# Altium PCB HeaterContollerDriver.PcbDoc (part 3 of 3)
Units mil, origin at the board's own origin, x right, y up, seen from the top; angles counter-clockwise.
Board outline 11550 x 4775 mil, 6 copper layers (Top Layer, GND1, P, N, GND2, Bottom Layer), stack 62.668 mil thick; 274 components, 133 nets, 711 pads, 145 vias.
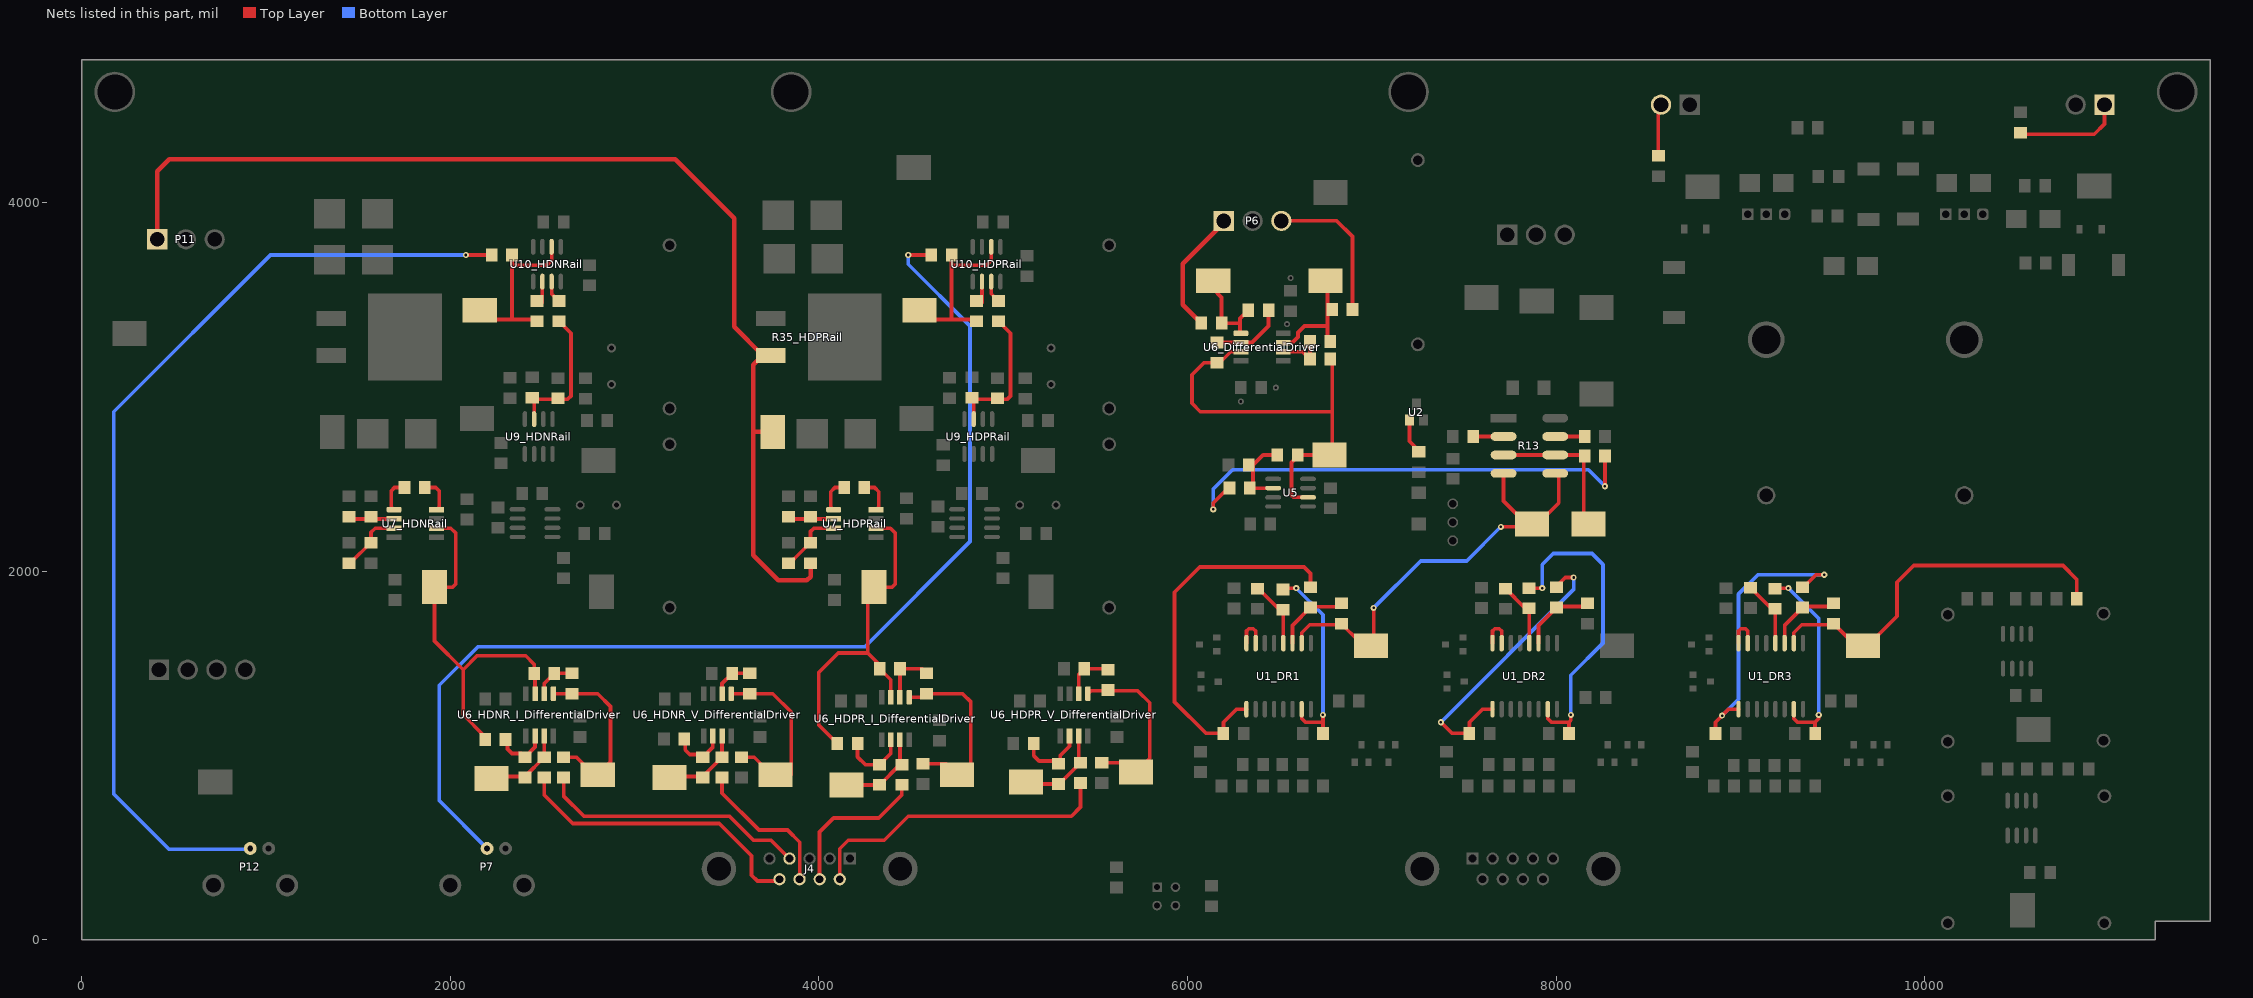
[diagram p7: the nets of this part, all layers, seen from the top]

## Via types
v1: diameter 33, hole 14, Top Layer to Bottom Layer, 145 vias

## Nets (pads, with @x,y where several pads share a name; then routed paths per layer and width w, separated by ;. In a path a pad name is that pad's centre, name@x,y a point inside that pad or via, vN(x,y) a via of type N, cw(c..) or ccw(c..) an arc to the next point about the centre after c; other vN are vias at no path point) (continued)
NetJ4_4: J4.4 R28_HDNR_I_DifferentialDriver.2 | length 1476.4
  Top Layer w20: R28_HDNR_I_DifferentialDriver.2@2615.12,879.88 2615.12,780.12 2725.24,670 3515,670 3645,540 3740,540 3842,438 J4.4@3842,430
NetJ4_6: J4.6 R31_HDPR_V_DifferentialDriver.2 | length 1695.6
  Top Layer w20: J4.6@4113.58,328.09 4113.58,493.58 4160,540 4355,540 4485,670 5370.12,670 5420,719.88 R31_HDPR_V_DifferentialDriver.2@5420,849.88
NetJ4_7: J4.7 R31_HDPR_I_DifferentialDriver.2 | length 850.1
  Top Layer w20: J4.7@4004,318 4004,584 4080,660 4325,660 4450,785 R31_HDPR_I_DifferentialDriver.2@4450,839.88
NetJ4_8: J4.8 R31_HDNR_V_DifferentialDriver.2 | length 826.9
  Top Layer w20: R31_HDNR_V_DifferentialDriver.2@3475,879.76 3475,795 3675,595 3830,595 3896,529 J4.8@3896,318
NetJ4_9: J4.9 R31_HDNR_I_DifferentialDriver.2 | length 1627.8
  Top Layer w20: R31_HDNR_I_DifferentialDriver.2@2510.12,879.88 2510.12,784.88 2665,630 3460,630 3635,455 3635,350 3667,318 J4.9@3788,318
NetP7_1: P7.1 R46_HDPRail.2 | length 6014.4
  Top Layer w20: v1(4485,3715) R46_HDPRail.2@4609.88,3715
  Bottom Layer w20: P7.1@2200,495 1940,755 1940,1380 2150,1590 4250,1590 4820,2160 4820,3330 4485,3665 v1(4485,3715)
NetP12_1: P12.1 R46_HDNRail.2 | length 5350.4
  Top Layer w20: v1(2085,3715) R46_HDNRail.2@2224.88,3715
  Bottom Layer w20: P12.1@920,500 910,490 475,490 175,790 175,2865 1025,3715 v1(2085,3715)
NetP13_1: P13.1 R53.1 | length 572.8
  Top Layer w20: R53.1@10520.12,4370.5 10920.12,4370.5 10975.12,4425.5 P13.1@10975.12,4520.5
NetP14_2: P14.2 R54.1 | length 275.8
  Top Layer w20: R54.1@8555,4260.5 8555,4516.5 P14.2@8569,4530.5
NetR1_DR1_1: R1_DR1.1 R3_DR1.1 U1_DR1.12 | length 324
  Top Layer w20: R3_DR1.1@6380,1910.12 R1_DR1.1@6492.95,1797.17 ; R1_DR1.1@6517.24,1772.17 6519.88,1769.53 U1_DR1.12@6519.88,1609.02
NetR1_DR1_2: R1_DR1.2 R5_DR1.1 U1_DR1.7 | length 1108.8
  Top Layer w20: R1_DR1.2@6517.24,1907.4 v1(6590,1907.4) ; U1_DR1.7@6619.88,1264.76 6619.88,1199.88 6640,1179.76 6735,1179.76 ; v1(6735,1219.76) 6735,1179.76 ; R5_DR1.1@6735.12,1119.76 6735,1119.88 6735,1179.76
  Bottom Layer w20: v1(6590,1907.4) 6735,1762.4 v1(6735,1219.76)
NetR1_DR2_1: R1_DR2.1 R3_DR2.1 U1_DR2.12 | length 336.2
  Top Layer w20: R3_DR2.1@7725,1905.12 7832.83,1797.28 R1_DR2.1@7852.24,1797.28 ; R1_DR2.1@7852.24,1772.28 7854.88,1769.65 U1_DR2.12@7854.88,1609.13
NetR1_DR2_2: R1_DR2.2 R5_DR2.1 U1_DR2.7 | length 1760.1
  Top Layer w20: R1_DR2.2@7852.24,1907.52 v1(7925,1907.52) ; U1_DR2.7@7954.88,1264.88 U1_DR2.7@7954.88,1250.87 7954.88,1200 7975,1179.88 8070,1179.88 ; R5_DR2.1@8070.12,1119.88 8070,1120 8070,1179.88 ; v1(8080,1219.76) 8080,1189.88 8070,1179.88
  Bottom Layer w20: v1(7925,1907.52) 7925,2035 7985,2095 8195,2095 8255,2035 8255,1610 8080,1435 v1(8080,1219.76)
NetR1_DR3_1: R1_DR3.1 R3_DR3.1 U1_DR3.12 | length 323.8
  Top Layer w20: R3_DR3.1@9055,1910.12 R1_DR3.1@9167.83,1797.28 ; R1_DR3.1@9187.24,1772.28 9189.88,1769.65 U1_DR3.12@9189.88,1609.13
NetR1_DR3_2: R1_DR3.2 R5_DR3.1 U1_DR3.7 | length 1125.4
  Top Layer w20: R1_DR3.2@9187.24,1907.52 v1(9260,1907.52) ; U1_DR3.7@9289.88,1264.88 U1_DR3.7@9289.88,1250.87 9289.88,1200 9310,1179.88 9405,1179.88 ; R5_DR3.1@9405.12,1119.88 9405,1120 9405,1179.88 ; v1(9425,1220) 9425,1199.88 9405,1179.88
  Bottom Layer w20: v1(9260,1907.52) 9425,1742.52 v1(9425,1220)
NetR8_DR1_1: R8_DR1.1 R11_DR1.2 U1_DR1.1 | length 2173.5
  Top Layer w20: U1_DR1.1@6319.88,1250.75 6265.87,1250.75 6195,1179.88 6195,1119.76 6100,1119.76 5930,1289.76 5930,1885 6067.28,2022.28 6632.24,2022.28 ; 6487.28,2022.28 6632.24,2022.28 ; R11_DR1.2@6667.24,1912.4 6667.24,1987.28 6632.24,2022.28
NetR8_DR2_1: R8_DR2.1 R11_DR2.2 U1_DR2.1 | length 1594.8
  Top Layer w20: v1(7375,1179.88) 7435,1119.88 7530,1119.88 7530,1180 7600.87,1250.87 U1_DR2.1@7654.88,1250.87 ; R11_DR2.2@8002.24,1912.52 8002.24,1917.24 8050,1965 v1(8095,1965)
  Bottom Layer w20: v1(7375,1179.88) 8095,1899.88 v1(8095,1965)
NetR8_DR3_1: R8_DR3.1 R11_DR3.2 U1_DR3.1 | length 1572.7
  Top Layer w20: R8_DR3.1@8865,1119.88 8865,1180 v1(8900.43,1215.43) 8935.87,1250.87 U1_DR3.1@8989.88,1250.87 ; R11_DR3.2@9337.24,1912.52 9337.24,1907.24 9410,1980 v1(9455,1980)
  Bottom Layer w20: v1(8900.43,1215.43) 8990,1305 8990,1875 9095,1980 v1(9455,1980)
NetR9_DR1_1: R9_DR1.1 R13.4 R13.5 TP1_DR1.1 TP2.1 U1_DR1.10 | length 2493.4
  Top Layer w20: U1_DR1.10@6619.88,1609.02 6619.88,1664.92 6663.23,1708.27 6828.5,1708.27 R9_DR1.1@6835,1714.76 6932.24,1617.52 6932.24,1622.52 TP1_DR1.1@6990,1564.76 ; TP1_DR1.1@6995,1594.76 7010,1609.76 v1(7010,1799.88) ; v1(7700,2239.88) 7854.88,2239.88 TP2.1@7870,2255 ; R13.4@7715,2530 7715,2380 7840,2255 TP2.1@7870,2255 ; R13.5@7995,2530 8015,2510 8015,2370 7915,2270 7885,2270 TP2.1@7870,2255
  Bottom Layer w20: v1(7010,1799.88) 7265.12,2055 7515.12,2055 v1(7700,2239.88)
NetR9_DR1_2: R9_DR1.2 R11_DR1.1 U1_DR1.11 | length 410.8
  Top Layer w20: U1_DR1.11@6569.88,1609.02 6569.88,1704.92 6672.24,1807.28 6817.28,1807.28 R9_DR1.2@6835,1825
NetR9_DR2_2: R9_DR2.2 R11_DR2.1 U1_DR2.11 | length 410.8
  Top Layer w20: U1_DR2.11@7904.88,1609.13 7904.88,1705.04 8007.24,1807.4 8152.28,1807.4 R9_DR2.2@8170,1825.12
NetR9_DR3_1: R9_DR3.1 R19.2 TP1_DR3.1 U1_DR3.10 | length 2100.6
  Top Layer w20: U1_DR3.10@9289.88,1609.13 9289.88,1665.04 9333.23,1708.39 9498.5,1708.39 R9_DR3.1@9505,1714.88 9602.24,1617.64 9602.24,1622.64 TP1_DR3.1@9660,1564.88 ; TP1_DR3.1@9665,1594.88 9689.88,1594.88 9850,1755 9850,1940 9940,2030 10750,2030 10825.12,1954.88 R19.2@10825.12,1850
NetR9_DR3_2: R9_DR3.2 R11_DR3.1 U1_DR3.11 | length 410.8
  Top Layer w20: U1_DR3.11@9239.88,1609.13 9239.88,1705.04 9342.24,1807.4 9487.28,1807.4 R9_DR3.2@9505,1825.12
NetR13_2: R13.2 R15.1 | length 164.9
  Top Layer w20: R15.1@7550.12,2730 R13.2@7715,2730
NetR13_3: R13.3 R13.6 R16.2 TP3.1 | length 821.2
  Top Layer w20: R13.3@7715,2630 R13.6@7995,2630 8150,2630 8150,2265 TP3.1@8165,2250
NetR13_7: R13.7 R14.2 | length 160
  Top Layer w20: R13.7@7995,2730 R14.2@8155,2730
NetR16_1: R16.1 R24.1 | length 2643.5
  Top Layer w20: v1@6140,2330 v1(6140,2335) 6140,2370 6220,2450 R24.1@6229.49,2450 ; v1@8265,2460 v1(8265.12,2460.12) R16.1@8265.12,2625
  Bottom Layer w20: v1(6140,2335) 6140,2445 6245,2550 8175.24,2550 v1(8265.12,2460.12)
NetR17_2: R17.2 U2.1 | length 185.7
  Top Layer w20: U2.1@7205,2820 7205,2705 R17.2@7255,2655
NetR23_1: R23.1 R24.2 R25.2 U5.2 | length 381.3
  Top Layer w20: U5.2@6465,2450 6355.49,2450 6355.49,2575 6410.49,2630 R23.1@6479.49,2630
NetR23_2: R23.2 R27_DifferentialDriver.1 R30_DifferentialDriver.1 TP7.1 U5.6 U6_DifferentialDriver.3 | length 2297.8
  Top Layer w20: U6_DifferentialDriver.3@6290,3190 6234.88,3190 6174.76,3129.88 R27_DifferentialDriver.1@6159.88,3129.88 6089.88,3129.88 6025,3065 6025,2910 6070,2865 6785,2865 ; U5.6@6653.98,2400 6574.49,2400 6564.49,2410 6564.49,2589 6605.49,2630 6784.49,2630 6785,2630.51 6785,2865 ; R30_DifferentialDriver.1@6784.49,3140.51 R30_DifferentialDriver.1@6775,3150 6785,3140 6785,2865
NetR26_DifferentialDriver_1: R26_DifferentialDriver.1 R27_DifferentialDriver.2 U6_DifferentialDriver.2 | length 402.4
  Top Layer w20: R27_DifferentialDriver.2@6159.88,3240.12 6160,3240 U6_DifferentialDriver.2@6290,3240 6349.88,3240 6440,3330.12 R26_DifferentialDriver.1@6440,3415
NetR26_DifferentialDriver_2: R26_DifferentialDriver.2 R28_DifferentialDriver.1 TP8_DifferentialDriver.1 U6_DifferentialDriver.1 | length 508.4
  Top Layer w20: TP8_DifferentialDriver.1@6139.88,3585 6139.88,3530.12 6185,3485 R28_DifferentialDriver.1@6185,3345 6274.88,3345 6284.88,3335 ; U6_DifferentialDriver.1@6290,3290 6284.88,3295.12 6284.88,3335 ; R26_DifferentialDriver.2@6329.76,3415 6284.88,3370.12 6284.88,3335
NetR26_HDNR_I_DifferentialDriver_1: R26_HDNR_I_DifferentialDriver.1 R27_HDNR_I_DifferentialDriver.2 U6_HDNR_I_DifferentialDriver.2 | length 227.8
  Top Layer w20: U6_HDNR_I_DifferentialDriver.2@2510.12,1335 2510.12,1389.88 R27_HDNR_I_DifferentialDriver.2@2565.24,1445 2660,1445 R26_HDNR_I_DifferentialDriver.1@2660.12,1445.12
NetR26_HDNR_I_DifferentialDriver_2: R26_HDNR_I_DifferentialDriver.2 R28_HDNR_I_DifferentialDriver.1 TP8_HDNR_I_DifferentialDriver.1 U6_HDNR_I_DifferentialDriver.1 | length 962.1
  Top Layer w20: U6_HDNR_I_DifferentialDriver.1@2560.12,1335 R26_HDNR_I_DifferentialDriver.2@2660,1335 ; R28_HDNR_I_DifferentialDriver.1@2615.12,990.12 2684.88,990.12 2780,895 TP8_HDNR_I_DifferentialDriver.1@2800.12,895 2870,964.88 2870,1265 2800.12,1334.88 R26_HDNR_I_DifferentialDriver.2@2660.12,1334.88
NetR26_HDNR_V_DifferentialDriver_1: R26_HDNR_V_DifferentialDriver.1 R27_HDNR_V_DifferentialDriver.2 U6_HDNR_V_DifferentialDriver.2 | length 227.8
  Top Layer w20: U6_HDNR_V_DifferentialDriver.2@3475,1334.88 3475,1389.76 R27_HDNR_V_DifferentialDriver.2@3530.12,1444.88 3624.88,1444.88 R26_HDNR_V_DifferentialDriver.1@3625,1445
NetR26_HDNR_V_DifferentialDriver_2: R26_HDNR_V_DifferentialDriver.2 R28_HDNR_V_DifferentialDriver.1 TP8_HDNR_V_DifferentialDriver.1 U6_HDNR_V_DifferentialDriver.1 | length 1015.7
  Top Layer w20: U6_HDNR_V_DifferentialDriver.1@3525,1334.88 R26_HDNR_V_DifferentialDriver.2@3624.88,1334.88 ; R28_HDNR_V_DifferentialDriver.1@3580,990 3650,990 3745.12,894.88 TP8_HDNR_V_DifferentialDriver.1@3765,894.88 3850,894.88 3850,1235 3750.24,1334.76 R26_HDNR_V_DifferentialDriver.2@3625,1334.76
NetR26_HDPR_I_DifferentialDriver_1: R26_HDPR_I_DifferentialDriver.1 R27_HDPR_I_DifferentialDriver.2 U6_HDPR_I_DifferentialDriver.2 | length 275.3
  Top Layer w20: U6_HDPR_I_DifferentialDriver.2@4440,1315 4440,1469.88 R26_HDPR_I_DifferentialDriver.1@4560.24,1469.88 ; R26_HDPR_I_DifferentialDriver.1@4584.88,1445 R26_HDPR_I_DifferentialDriver.1@4585,1445.12
NetR26_HDPR_I_DifferentialDriver_2: R26_HDPR_I_DifferentialDriver.2 R28_HDPR_I_DifferentialDriver.1 TP8_HDPR_I_DifferentialDriver.1 U6_HDPR_I_DifferentialDriver.1 | length 1041.6
  Top Layer w20: U6_HDPR_I_DifferentialDriver.1@4490,1315 4565.12,1315 R26_HDPR_I_DifferentialDriver.2@4585,1334.88 4779.88,1334.88 4825,1289.76 4825,895 TP8_HDPR_I_DifferentialDriver.1@4750,895 4689.88,955.12 R28_HDPR_I_DifferentialDriver.1@4565,955.12
NetR26_HDPR_V_DifferentialDriver_1: R26_HDPR_V_DifferentialDriver.1 R27_HDPR_V_DifferentialDriver.2 U6_HDPR_V_DifferentialDriver.2 | length 272.8
  Top Layer w20: U6_HDPR_V_DifferentialDriver.2@5410,1334.88 5410,1439.88 R27_HDPR_V_DifferentialDriver.2@5440.12,1470 R26_HDPR_V_DifferentialDriver.1@5565.12,1470 ; R26_HDPR_V_DifferentialDriver.1@5559.88,1444.88 R26_HDPR_V_DifferentialDriver.1@5560,1445
NetR26_HDPR_V_DifferentialDriver_2: R26_HDPR_V_DifferentialDriver.2 R28_HDPR_V_DifferentialDriver.1 TP8_HDPR_V_DifferentialDriver.1 U6_HDPR_V_DifferentialDriver.1 | length 980.6
  Top Layer w20: U6_HDPR_V_DifferentialDriver.1@5460,1334.76 5475.24,1350 5730,1350 5795,1285 5795,984.65 TP8_HDPR_V_DifferentialDriver.1@5720,909.65 5669.53,960.12 R28_HDPR_V_DifferentialDriver.1@5535,960.12
NetR27_HDNR_I_DifferentialDriver_1: R27_HDNR_I_DifferentialDriver.1 R30_HDNR_I_DifferentialDriver.1 TP10_HDNRail.1 U6_HDNR_I_DifferentialDriver.3 U7_HDNRail.6 | length 2053.8
  Top Layer w20: U7_HDNRail.6@1925,2233 2003.12,2233 2030,2206.12 2030,1929.88 2013.12,1913 TP10_HDNRail.1@1915,1913 1915,1620 2070,1465 ; R30_HDNR_I_DifferentialDriver.1@2200,1105 2185,1105 2070,1220 2070,1465 ; R27_HDNR_I_DifferentialDriver.1@2455,1430 R27_HDNR_I_DifferentialDriver.1@2455,1445 2455,1495 2410,1540 2145,1540 2070,1465 ; U6_HDNR_I_DifferentialDriver.3@2460.12,1335 R27_HDNR_I_DifferentialDriver.1@2460.12,1439.88
NetR27_HDPR_I_DifferentialDriver_1: R27_HDPR_I_DifferentialDriver.1 R30_HDPR_I_DifferentialDriver.1 TP10_HDPRail.1 U6_HDPR_I_DifferentialDriver.3 U7_HDPRail.6 | length 1913.5
  Top Layer w20: R30_HDPR_I_DifferentialDriver.1@4099.88,1065 4000,1164.88 4000,1450 4105,1555 4265,1555 ; U7_HDPRail.6@4310,2233 4388.12,2233 4415,2206.12 4415,1929.88 4398.12,1913 TP10_HDPRail.1@4300,1913 4265,1878 4265,1555 ; U6_HDPR_I_DifferentialDriver.3@4390,1315 4390,1409.88 R27_HDPR_I_DifferentialDriver.1@4329.88,1470 4329.88,1490.12 4265,1555
NetR29_DifferentialDriver_1: R29_DifferentialDriver.1 R30_DifferentialDriver.2 U6_DifferentialDriver.6 | length 311.2
  Top Layer w20: U6_DifferentialDriver.6@6520,3190 6589.76,3190 ; U6_DifferentialDriver.6@6534.88,3190 6624.76,3190 R30_DifferentialDriver.2@6664.76,3150 R29_DifferentialDriver.1@6664.76,3245
NetR29_DifferentialDriver_2: R29_DifferentialDriver.2 R31_DifferentialDriver.1 TP9_DifferentialDriver.1 U6_DifferentialDriver.7 | length 647.3
  Top Layer w20: U6_DifferentialDriver.7@6520,3240 6569.88,3240 6599.88,3270 6599.88,3295 6634.88,3330 6749.88,3330 6760,3319.88 ; TP9_DifferentialDriver.1@6760,3590 6760,3319.88 ; R29_DifferentialDriver.2@6775,3245 6760,3260 6760,3319.88
NetR29_HDNR_I_DifferentialDriver_1: R29_HDNR_I_DifferentialDriver.1 R30_HDNR_I_DifferentialDriver.2 U6_HDNR_I_DifferentialDriver.6 | length 321.3
  Top Layer w20: R30_HDNR_I_DifferentialDriver.2@2310.24,1105 2310.24,1034.76 2335,1010 2385.24,1010 R29_HDNR_I_DifferentialDriver.1@2405.12,990.12 2460.12,1045.12 U6_HDNR_I_DifferentialDriver.6@2460.12,1105
NetR29_HDNR_I_DifferentialDriver_2: R29_HDNR_I_DifferentialDriver.2 R31_HDNR_I_DifferentialDriver.1 TP9_HDNR_I_DifferentialDriver.1 U6_HDNR_I_DifferentialDriver.7 | length 445.4
  Top Layer w20: TP9_HDNR_I_DifferentialDriver.1@2225.12,890 2230,885.12 2405.12,885.12 R31_HDNR_I_DifferentialDriver.1@2510.12,990.12 U6_HDNR_I_DifferentialDriver.7@2510.12,1105
NetR29_HDNR_V_DifferentialDriver_1: R29_HDNR_V_DifferentialDriver.1 R30_HDNR_V_DifferentialDriver.2 U6_HDNR_V_DifferentialDriver.6 | length 344.1
  Top Layer w20: R30_HDNR_V_DifferentialDriver.2@3275.12,1084.88 3275.12,1104.88 3275.12,1029.88 3300,1005 3355,1005 R29_HDNR_V_DifferentialDriver.1@3370,990 3425,1045 U6_HDNR_V_DifferentialDriver.6@3425,1104.88
NetR29_HDNR_V_DifferentialDriver_2: R29_HDNR_V_DifferentialDriver.2 R31_HDNR_V_DifferentialDriver.1 TP9_HDNR_V_DifferentialDriver.1 U6_HDNR_V_DifferentialDriver.7 | length 445.4
  Top Layer w20: TP9_HDNR_V_DifferentialDriver.1@3190,889.88 3194.88,885 3370,885 R31_HDNR_V_DifferentialDriver.1@3475,990 U6_HDNR_V_DifferentialDriver.7@3475,1104.88
NetR29_HDPR_I_DifferentialDriver_1: R29_HDPR_I_DifferentialDriver.1 R30_HDPR_I_DifferentialDriver.2 U6_HDPR_I_DifferentialDriver.6 | length 370.2
  Top Layer w20: R30_HDPR_I_DifferentialDriver.2@4210.12,1065 4210.12,991.88 4252,950 R29_HDPR_I_DifferentialDriver.1@4330,950 4390,1010 U6_HDPR_I_DifferentialDriver.6@4390,1085
NetR29_HDPR_I_DifferentialDriver_2: R29_HDPR_I_DifferentialDriver.2 R31_HDPR_I_DifferentialDriver.1 TP9_HDPR_I_DifferentialDriver.1 U6_HDPR_I_DifferentialDriver.7 | length 470.4
  Top Layer w20: TP9_HDPR_I_DifferentialDriver.1@4150.24,839.76 R29_HDPR_I_DifferentialDriver.2@4330,839.76 R31_HDPR_I_DifferentialDriver.1@4440.35,950.12 ; R31_HDPR_I_DifferentialDriver.1@4440,950.47 U6_HDPR_I_DifferentialDriver.7@4440,1085
NetR29_HDPR_V_DifferentialDriver_1: R29_HDPR_V_DifferentialDriver.1 R30_HDPR_V_DifferentialDriver.2 U6_HDPR_V_DifferentialDriver.6 | length 377.9
  Top Layer w20: R30_HDPR_V_DifferentialDriver.2@5165.12,1065 5165.12,1000 5195.12,970 5310,970 5310,1000 5360,1050 U6_HDPR_V_DifferentialDriver.6@5360,1104.88
NetR29_HDPR_V_DifferentialDriver_2: R29_HDPR_V_DifferentialDriver.2 R31_HDPR_V_DifferentialDriver.1 TP9_HDPR_V_DifferentialDriver.1 U6_HDPR_V_DifferentialDriver.7 | length 474.2
  Top Layer w20: TP9_HDPR_V_DifferentialDriver.1@5125,889.88 TP9_HDPR_V_DifferentialDriver.1@5129.88,885 ; TP9_HDPR_V_DifferentialDriver.1@5135.24,844.88 R29_HDPR_V_DifferentialDriver.2@5300,844.88 5304.76,844.88 R31_HDPR_V_DifferentialDriver.1@5420,960.12 ; R31_HDPR_V_DifferentialDriver.1@5410,970.12 U6_HDPR_V_DifferentialDriver.7@5410,1104.88
NetR32_HDNRail_1: R32_HDNRail.1 U7_HDNRail.8 | length 185.7
  Top Layer w20: R32_HDNRail.1@1870,2453 1922,2453 1940,2435 1940,2348 U7_HDNRail.8@1925,2333
NetR32_HDNRail_2: R32_HDNRail.2 U7_HDNRail.1 | length 179.7
  Top Layer w20: U7_HDNRail.1@1695,2333 1680,2348 1680,2435 1698,2453 R32_HDNRail.2@1744,2453
NetR32_HDPRail_1: R32_HDPRail.1 U7_HDPRail.8 | length 182.7
  Top Layer w20: R32_HDPRail.1@4255,2453 4302,2453 4325,2430 4325,2348 U7_HDPRail.8@4310,2333
NetR32_HDPRail_2: R32_HDPRail.2 U7_HDPRail.1 | length 176.7
  Top Layer w20: U7_HDPRail.1@4080,2333 4065,2348 4065,2430 4088,2453 R32_HDPRail.2@4129,2453
NetR33_HDNRail_1: R33_HDNRail.1 R34_HDNRail.2 U7_HDNRail.3 | length 376.9
  Top Layer w20: R33_HDNRail.1@1450,2035 R34_HDNRail.2@1582.5,2167.5 ; R34_HDNRail.2@1570,2155 1570,2210 1593,2233 U7_HDNRail.3@1695,2233
NetR33_HDPRail_1: R33_HDPRail.1 R34_HDPRail.2 U7_HDPRail.3 | length 362.2
  Top Layer w20: R33_HDPRail.1@3835,2035 3905,2105 3955,2155 3955,2215 3973,2233 U7_HDPRail.3@4080,2233
NetR36_HDNRail_2: R36_HDNRail.2 R37_HDNRail.2 U7_HDNRail.2 | length 246.7
  Top Layer w20: R37_HDNRail.2@1450,2287 1454,2283 U7_HDNRail.2@1695,2283
NetR36_HDPRail_2: R36_HDPRail.2 R37_HDPRail.2 U7_HDPRail.2 | length 246.7
  Top Layer w20: R37_HDPRail.2@3835,2287 3839,2283 U7_HDPRail.2@4080,2283
NetR42_HDNRail_1: R42_HDNRail.1 R43_HDNRail.2 R45_HDNRail.2 U9_HDNRail.3 | length 770.2
  Top Layer w20: U9_HDNRail.3@2455,2824.37 2455,2923 2445,2933 R43_HDNRail.2@2589,2933 ; R45_HDNRail.2@2590,3354.88 2655,3289.88 2655,2949.88 2638.12,2933 R43_HDNRail.2@2589,2933 ; R43_HDNRail.2@2595,2927 R43_HDNRail.2@2589,2933
NetR42_HDPRail_1: R42_HDPRail.1 R43_HDPRail.2 R45_HDPRail.2 U9_HDPRail.3 | length 770.2
  Top Layer w20: U9_HDPRail.3@4840,2824.37 4840,2923 4830,2933 R43_HDPRail.2@4974,2933 ; R45_HDPRail.2@4975,3354.88 5040,3289.88 5040,2949.88 5023.12,2933 R43_HDPRail.2@4974,2933 ; R43_HDPRail.2@4980,2927 R43_HDPRail.2@4974,2933
NetR44_HDNRail_1: R44_HDNRail.1 U10_HDNRail.2 | length 78.5
  Top Layer w20: R44_HDNRail.1@2500,3455 U10_HDNRail.2@2500,3533.51
NetR44_HDNRail_2: R44_HDNRail.2 R46_HDNRail.1 TP14_HDNRail.1 U10_HDNRail.6 | length 1012.6
  Top Layer w20: TP14_HDNRail.1@2150,3364.88 2335,3364.88 ; 2335.12,3659.88 2524.88,3659.88 2550,3685 U10_HDNRail.6@2550,3780 ; R46_HDNRail.1@2335.12,3733 2335.12,3365 2335,3364.88 ; R44_HDNRail.2@2470,3354.88 2460,3364.88 2335,3364.88
NetR44_HDPRail_1: R44_HDPRail.1 U10_HDPRail.2 | length 78.5
  Top Layer w20: R44_HDPRail.1@4885,3455 U10_HDPRail.2@4885,3533.51
NetR44_HDPRail_2: R44_HDPRail.2 R46_HDPRail.1 TP14_HDPRail.1 U10_HDPRail.6 | length 1012.6
  Top Layer w20: TP14_HDPRail.1@4535,3364.88 4720,3364.88 ; 4720.12,3659.88 4909.88,3659.88 4935,3685 U10_HDPRail.6@4935,3780 ; R46_HDPRail.1@4720.12,3733 4720.12,3365 4720,3364.88 ; R44_HDPRail.2@4855,3354.88 4845,3364.88 4720,3364.88
NetR45_HDNRail_1: R45_HDNRail.1 U10_HDNRail.3 | length 122
  Top Layer w20: U10_HDNRail.3@2550,3570.51 2550,3505.12 R45_HDNRail.1@2590,3465.12
NetR45_HDPRail_1: R45_HDPRail.1 U10_HDPRail.3 | length 122
  Top Layer w20: U10_HDPRail.3@4935,3570.51 4935,3505.12 R45_HDPRail.1@4975,3465.12
NetU1_DR1_15: U1_DR1.15 U1_DR1.16 | length 191.9
  Top Layer w20: U1_DR1.16@6319.88,1609.02 6319.88,1674.92 6332.24,1687.28 6357.24,1687.28 6369.88,1674.65 U1_DR1.15@6369.88,1609.02
NetU1_DR2_15: U1_DR2.15 U1_DR2.16 | length 191.9
  Top Layer w20: U1_DR2.16@7654.88,1609.13 7654.88,1675.04 7667.24,1687.4 7692.24,1687.4 7704.88,1674.76 U1_DR2.15@7704.88,1609.13
NetU1_DR3_15: U1_DR3.15 U1_DR3.16 | length 191.9
  Top Layer w20: U1_DR3.16@8989.88,1609.13 8989.88,1675.04 9002.24,1687.4 9027.24,1687.4 9039.88,1674.76 U1_DR3.15@9039.88,1609.13
OUTN: P6.3 R31_DifferentialDriver.2 | length 815.8
  Top Layer w20: P6.3@6509.5,3900 6810,3900 6895.12,3814.88 R31_DifferentialDriver.2@6895.12,3420
OUTP: P6.1 R28_DifferentialDriver.2 | length 685.9
  Top Layer w25: R28_DifferentialDriver.2@6074.76,3345 5974.76,3445 5974.76,3667.76 P6.1@6202.25,3895.25
R: P11.1 R34_HDPRail.1 R35_HDPRail.3 TP20_HDPRail.1 | length 6168.6
  Top Layer w20: R35_HDPRail.3@3695,3169.88 R35_HDPRail.3@3740,3169.88
  Top Layer w25: P11.1@410,3790 410,4170 475,4235 3220,4235 3540,3915 3540,3324.88 3695,3169.88 3645,3119.88 3645,2085 3780,1950 3935,1950 3955,1970 R34_HDPRail.1@3955,2035 ; 3650,2755 TP20_HDPRail.1@3750,2755
pads on no net: F1_HDNRail.1 F1_HDNRail.2 F1_HDPRail.1 F1_HDPRail.2 F2_HDNRail.1 F2_HDNRail.2 F2_HDPRail.1 F2_HDPRail.2 J1.4 J1.5 J1.9 J4.5 P7.3 P7.4 P12.3 P12.4 R35_HDNRail. R35_HDPRail. U1_DR1.8 U1_DR1.9 U1_DR2.8 U1_DR2.9 U1_DR3.8 U1_DR3.9 U3.1 U3.5 U3.8 U4.1 U4.5 U4.8 U5.1 U5.5 U5.8 U8_HDNRail.1 U8_HDNRail.5 U8_HDNRail.8 U8_HDPRail.1 U8_HDPRail.5 U8_HDPRail.8 U9_HDNRail.1 U9_HDNRail.5 U9_HDNRail.8 U9_HDPRail.1 U9_HDPRail.5 U9_HDPRail.8 U10_HDNRail.1 U10_HDNRail.5 U10_HDNRail.8 U10_HDPRail.1 U10_HDPRail.5 U10_HDPRail.8 U11.4 U11.5 U12.4 U12.5

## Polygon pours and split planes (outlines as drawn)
GND on GND1 (split plane): 11529.9,120.1 11250,120.1 11246.08,119.71 11242.31,118.57 11238.83,116.71 11235.79,114.21 11233.29,111.17 11231.43,107.69 11230.29,103.92 11229.9,100 11229.9,20.1 20.1,20.1 20.1,4754.9 11529.9,4754.9
+15 on P (split plane): 11529.9,120.1 11250,120.1 11246.08,119.71 11242.31,118.57 11238.83,116.71 11235.79,114.21 11233.29,111.17 11231.43,107.69 11230.29,103.92 11229.9,100 11229.9,20.1 20.1,20.1 20.1,4754.9 11529.9,4754.9
-15 on N (split plane): 11529.9,120.1 11250,120.1 11246.08,119.71 11242.31,118.57 11238.83,116.71 11235.79,114.21 11233.29,111.17 11231.43,107.69 11230.29,103.92 11229.9,100 11229.9,20.1 20.1,20.1 20.1,4754.9 11529.9,4754.9
GND on GND2 (split plane): 11529.9,120.1 11250,120.1 11246.08,119.71 11242.31,118.57 11238.83,116.71 11235.79,114.21 11233.29,111.17 11231.43,107.69 11230.29,103.92 11229.9,100 11229.9,20.1 20.1,20.1 20.1,4754.9 11529.9,4754.9

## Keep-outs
Keep-Out Layer:
  lines w10: 25,25 11525,25 11525,4750 25,4750 25,25

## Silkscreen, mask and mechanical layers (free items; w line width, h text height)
Top Overlay:
  region: 3430,4705 2040,4705 2040,4325 3430,4325
  lines w10: 1990,1615 2930,1615 ; 1990.12,1615 1990.12,605 2930.12,605 2930.12,1615 ; 2015,1655 2015,3985 2015,4065 ; 2015,3285 2835,3285 2835,4070 ; 3880,605 4880,605 ; 3915,605 3915,1615 ; 3920,604.88 2955,604.88 2955,1615 3920,1615 4880,1615 ; 4400,1655 4400,3305 ; 4400,4070 4400,3305 ; 4880,604.88 5845,604.88 5845,1614.88 4880,1614.88 ; 4890,604.76 4890,1614.88 4890,604.88 4995,604.88 ; 5215,4070 5215,3305 4400,3305 ; 9780,2165 9780.12,4700.5 ; 1095,1655 3465,1655 3465,4070 1095,4070 1095,1655 ; 3510,1655 5850,1655 5850,4070 3510,4070 3510,1655 ; 5885,699.76 7185,699.76 7185,2055 5885,2055 5885,699.76 ; 5885,2845 7020,2845 7020,3665 5885,3665 5885,2845 ; 6000,2070 6000,2815 6915,2815 6915,2070 6000,2070 ; 7070,2085 8330,2085 8330,3145 7070,3145 7070,2085 ; 7222.76,697.6 8517.76,697.6 8517.76,2055 7222.76,2055 7222.76,697.6 ; 8365,2160 11140,2160 11140,4700.5 8365,4700.5 8365,2160 ; 8555,695 9855,695 9855,2055 8555,2055 8555,695 ; 9880,21 9880,2070 11210,2070 11210,21 9880,21
  text "HEATER DRIVER" at 4105,4610 h80
  text "DRIVER HT" at 965,4485 h60
  text "D1600454-v3" at 4170,4435 h80
  text "Board" at 5535,4375 h60
  text "MARCHAND AMPLIFIER" at 850,4325 h60
  text "MARCHAND" at 5445,4240 h60
  text "GND" at 4245,4120 h50
  text "AMPLIFIER" at 5430,4115 h60
  text "-V_MON" at 2035,3950 h60
  text "+V_MON" at 4440,3940 h60
  text "GND" at 6710,3795 h50
  text "GND" at 410,3320 h50
  text "+V" at 7540,3300 h50
  text "GND" at 7820,3300 h50
  text "-V" at 8165,3300 h50
  text "DIFFERENTIAL" at 5980,2895 h60 r90
  text "DRIVER" at 6955,2880 h60 r90
  text "VOLTAGE REGULATOR -15v" at 8470,2565 h60 r90
  text "ON" at 7530,2215 h35
  text "VOLTAGE REGULATOR +15v" at 11052,2210 h60 r90
  text "1-2" at 7530,2145 h40
  text "RELAY" at 7160,2115 h60 r90
  text "SUMMING NODE" at 6094.49,2100 h60 r90
  text "LOW PASS FILTER" at 9920,1985 h60
  text "V_MON" at 4455,1855 h40
  text "I_MON" at 3670,1835 h40
  text "V_MON" at 2050,1805 h40
  text "I_MON" at 1255,1795 h40
  text "ADC" at 4455,1755 h40
  text "ADC" at 3674.88,1745 h40
  text "HEATER_DRIVER_CIRCUIT_NEGATIVE_RAIL" at 1190,1715 h60 r90
  text "HEATER_DRIVER_CIRCUIT_POSITIVE_RAIL" at 3610,1715 h60 r90
  text "ADC" at 2050,1710 h40
  text "ADC" at 1255,1700 h40
  text "POS_RAIL_I" at 4850,1030 h60 r90
  text "POS_RAIL_V" at 5815,1005 h60 r90
  text "NEG_RAIL_I" at 2900,995 h60 r90
  text "NEG_RAIL_V" at 3880,995 h60 r90
  text "GND" at 870,785 h50
  text "DR1_TEST PATH" at 5980,744.76 h60 r90
  text "DR2_ RELAY_ACTUATION" at 7312.76,732.6 h60 r90
  text "DR3_MAIN_HEATER_PATH" at 8645,720 h60 r90
  text "DIFF_DRIVER" at 3054.88,660 h60 r90
  text "DIFF_DRIVER" at 2090.12,635 h60 r90
  text "DIFF_DRIVER" at 4005,630 h60 r90
  text "DIFF_DRIVER" at 4980,630 h60 r90
  text "NEGATIVE" at 45,445 h60
  text "POSITIVE" at 1335,430 h60
  text "I&V" at 4655,405 h60
  text "DRIVE" at 50,290 h60
  text "MONITOR" at 4640,260 h60
  text "DRIVE" at 1355,250 h60
  text "DAC INPUT" at 6540,210 h60
  text "MONITOR" at 50,135 h60
  text "To ADC" at 4630,95 h60
  text "MONITOR" at 1355,90 h60
Mechanical 1:
  lines w10: -170,60 -150,0 ; -170,4715 -150,4775 ; -160,0 -140,0 ; -160,4775 -140,4775 ; -150,2106.59 -150,0 ; -150,2668.41 -150,4775 ; -130,60 -150,0 ; -130,4715 -150,4775 ; 0,-220 0,-200 ; 0,-155 0,-135 ; 0,-70 0,-50 ; 10,-465 10,-445 ; 60,-230 0,-210 ; 60,-190 0,-210 ; 60,-165 0,-145 ; 60,-125 0,-145 ; 60,-80 0,-60 ; 60,-40 0,-60 ; 70,-475 10,-455 ; 70,-435 10,-455 ; 211.57,-145 0,-145 ; 703.43,-145 915,-145 ; 719.09,-60 0,-60 ; 855,-165 915,-145 ; 855,-125 915,-145 ; 915,-155 915,-135 ; 915,-125 915,-145 ; 975,-155 915,-135 ; 975,-115 915,-135 ; 1280.91,-60 2000,-60 ; 1281.58,-135 915,-135 ; 1444.09,-210 0,-210 ; 1833.42,-135 2200,-135 ; 1855,-290 1955,-290 ; 1895,-310 1955,-290 ; 1895,-270 1955,-290 ; 1940,-80 2000,-60 ; 1940,-40 2000,-60 ; 1955,-300 1955,-280 ; 2000,-70 2000,-50 ; 2005.91,-210 3450,-210 ; 2140,-155 2200,-135 ; 2140,-115 2200,-135 ; 2200,-300 2200,-280 ; 2200,-145 2200,-125 ; 2260,-310 2200,-290 ; 2260,-270 2200,-290 ; 2300,-290 2200,-290 ; 2445,-135 2445,-115 ; 2505,-145 2445,-125 ; 2505,-105 2445,-125 ; 2671.58,-125 2445,-125 ; 3223.42,-125 3450,-125 ; 3350,-210 3450,-210 ; 3390,-145 3450,-125 ; 3390,-105 3450,-125 ; 3450,-65 3450,-45 ; 3510,-145 3450,-125 ; 3510,-105 3450,-125 ; 3510,-75 3450,-55 ; 3510,-35 3450,-55 ; 3625,-410 3625,-390 ; 3625,-220 3625,-200 ; 3674.08,-125 3450,-125 ; 3685,-420 3625,-400 ; 3685,-380 3625,-400 ; 3685,-230 3625,-210 ; 3685,-190 3625,-210 ; 3699.08,-400 3625,-400 ; 3725,-210 3625,-210 ; 3790,-305 3790,-285 ; 3850,-315 3790,-295 ; 3850,-275 3790,-295 ; 4200.92,-400 4275,-400 ; 4215,-420 4275,-400 ; 4215,-380 4275,-400 ; 4225.92,-125 4450,-125 ; 4275,-410 4275,-390 ; 4390,-145 4450,-125 ; 4390,-105 4450,-125 ; 4450,-135 4450,-115 ; 4565,-220 4565,-200 ; 4625,-230 4565,-210 ; 4625,-190 4565,-210 ; 4901.58,-210 4565,-210 ; 5081.58,-55 3450,-55 ; 5421.58,-295 3790,-295 ; 5453.42,-210 5790,-210 ; 5484.09,-455 10,-455 ; 5633.42,-55 7265,-55 ; 5730,-230 5790,-210 ; 5730,-190 5790,-210 ; 5790,-220 5790,-200 ; 5835,-135 5835,-115 ; 5895,-145 5835,-125 ; 5895,-105 5835,-125 ; 5973.42,-295 7605,-295 ; 5980,-220 5980,-200 ; 6040,-230 5980,-210 ; 6040,-190 5980,-210 ; 6085.91,-455 11560,-455 ; 6274.08,-125 5835,-125 ; 6294.08,-210 5980,-210 ; 6825.92,-125 7265,-125 ; 6835.92,-210 7150,-210 ; 7090,-230 7150,-210 ; 7090,-190 7150,-210 ; 7150,-220 7150,-200 ; 7205,-145 7265,-125 ; 7205,-105 7265,-125 ; 7205,-75 7265,-55 ; 7205,-35 7265,-55 ; 7265,-135 7265,-115 ; 7325,-75 7265,-55 ; 7325,-35 7265,-55 ; 7545,-315 7605,-295 ; 7545,-275 7605,-295 ; 7605,-305 7605,-285 ; 8385,-150 8385,-130 ; 8445,-160 8385,-140 ; 8445,-120 8385,-140 ; 9126.59,-55 7265,-55 ; 9688.41,-55 11550,-55 ; 9691.58,-140 8385,-140 ; 10243.42,-140 11550,-140 ; 11490,-160 11550,-140 ; 11490,-120 11550,-140 ; 11490,-75 11550,-55 ; 11490,-35 11550,-55 ; 11500,-475 11560,-455 ; 11500,-435 11560,-455 ; 11550,-150 11550,-130 ; 11550,-65 11550,-45 ; 11560,-465 11560,-445 ; 3450,-210 3390,-230 3450,-210 ; 3450,-210 3390,-190 3450,-210 ; 0,0 11250,0 11250,100 11550,100 11550,4775 0,4775 0,0 ; 3450,-220 3450,-200 3450,-220 ; 3450,-135 3450,-115 3450,-135 ; 7265,-65 7265,-45 7265,-65
  text "4775 (mil)" at -114.01,2116.59 h60 r90
  text "3815 (mil)" at 5091.58,-90.99 h60
  text "4285 (mil)" at 9136.59,-90.99 h60
  text "2000 (mil)" at 729.09,-95.99 h60
  text "1005 (mil)" at 2681.58,-160.99 h60
  text "1000 (mil)" at 3684.08,-160.99 h60
  text "1430 (mil)" at 6284.08,-160.99 h60
  text "1285 (mil)" at 1291.58,-170.99 h60
  text "3165 (mil)" at 9701.58,-175.99 h60
  text "915 (mil)" at 221.57,-180.99 h60
  text "3450 (mil)" at 1454.09,-245.99 h60
  text "1225 (mil)" at 4911.58,-245.99 h60
  text "1170 (mil)" at 6304.08,-245.99 h60
  text "3815 (mil)" at 5431.58,-330.99 h60
  text "175 (mil)" at 3301.57,-353.96 h60
  text "245 (mil)" at 1836.58,-433.96 h60
  text "650 (mil)" at 3709.08,-435.99 h60
  text "11550 (mil)" at 5494.09,-490.99 h60
Drill Drawing:
  circle w10: c100.62,6735.83 r33.33
  lines w10: 67.29,5202.5 67.29,5219.17 83.96,5235.83 67.29,5252.5 67.29,5269.17 83.96,5269.17 100.62,5252.5 117.29,5269.17 133.96,5269.17 133.96,5252.5 117.29,5235.83 133.96,5219.17 133.96,5202.5 117.29,5202.5 100.62,5219.17 83.96,5202.5 67.29,5202.5 ; 67.29,5502.5 133.96,5502.5 133.96,5569.17 67.29,5569.17 67.29,5502.5 ; 67.29,5719.17 133.96,5719.17 100.62,5652.5 67.29,5719.17 ; 67.29,5952.5 100.62,5969.17 133.96,5952.5 117.29,5985.83 133.96,6019.17 100.62,6002.5 67.29,6019.17 83.96,5985.83 67.29,5952.5 ; 67.29,6419.17 83.96,6419.17 100.62,6402.5 117.29,6419.17 133.96,6419.17 117.29,6435.83 133.96,6452.5 117.29,6452.5 100.62,6469.17 83.96,6452.5 67.29,6452.5 83.96,6435.83 67.29,6419.17
  lines w15: 7.5,5157.5 10598.56,5157.5 ; 7.5,6807.5 10598.56,6807.5 ; 558.38,5007.5 558.38,6957.5 ; 1158.22,5007.5 1158.22,6957.5 ; 2307.88,5007.5 2307.88,6957.5 ; 2813.76,5007.5 2813.76,6957.5 ; 3547.56,5007.5 3547.56,6957.5 ; 5047.11,5007.5 5047.11,6957.5 ; 5636.96,5007.5 5636.96,6957.5 ; 6382.76,5007.5 6382.76,6957.5 ; 7032.58,5007.5 7032.58,6957.5 ; 7886.35,5007.5 7886.35,6957.5 ; 9219.96,5007.5 9219.96,6957.5 ; 7.5,5007.5 10598.56,5007.5 10598.56,6957.5 7.5,6957.5 7.5,5007.5
  text "Symbol" at 97.5,6852.5 h72
  text "Count" at 603.38,6852.5 h72
  text "Hole Size" at 1203.22,6852.5 h72
  text "Plated" at 2352.88,6852.5 h72
  text "Hole Type" at 2858.76,6852.5 h72
  text "Drill Layer Pair" at 3592.56,6852.5 h72
  text "Via/Pad" at 5092.11,6852.5 h72
  text "Pad Shape" at 5681.96,6852.5 h72
  text "Template" at 6427.76,6852.5 h72
  text "Description" at 7077.58,6852.5 h72
  text "Hole Tolerance (+)" at 7931.35,6852.5 h72
  text "Hole Tolerance (-)" at 9264.96,6852.5 h72
  text "2" at 603.38,6702.5 h60
  text "75.00mil (1.905mm)" at 1203.22,6702.5 h60
  text "PTH" at 2352.88,6702.5 h60
  text "Round" at 2858.76,6702.5 h60
  text "Top Layer - Bottom Layer" at 3592.56,6702.5 h60
  text "Pad" at 5092.11,6702.5 h60
  text "Rounded" at 5681.96,6702.5 h60
  text "c254h190" at 6427.76,6702.5 h60
  text "2" at 603.38,6552.5 h60
  text "155.00mil (3.937mm)" at 1203.22,6552.5 h60
  text "PTH" at 2352.88,6552.5 h60
  text "Round" at 2858.76,6552.5 h60
  text "Top Layer - Bottom Layer" at 3592.56,6552.5 h60
  text "Pad" at 5092.11,6552.5 h60
  text "Rounded" at 5681.96,6552.5 h60
  text "c508h394" at 6427.76,6552.5 h60
  text "F" at 68.41,6542.51 h66.67
  text "4" at 603.38,6402.5 h60
  text "128.35mil (3.260mm)" at 1203.22,6402.5 h60
  text "PTH" at 2352.88,6402.5 h60
  text "Round" at 2858.76,6402.5 h60
  text "Top Layer - Bottom Layer" at 3592.56,6402.5 h60
  text "Pad" at 5092.11,6402.5 h60
  text "Rounded" at 5681.96,6402.5 h60
  text "c476h326" at 6427.76,6402.5 h60
  text "4" at 603.38,6252.5 h60
  text "190.00mil (4.826mm)" at 1203.22,6252.5 h60
  text "PTH" at 2352.88,6252.5 h60
  text "Round" at 2858.76,6252.5 h60
  text "Top Layer - Bottom Layer" at 3592.56,6252.5 h60
  text "Pad" at 5092.11,6252.5 h60
  text "Rounded" at 5681.96,6252.5 h60
  text "c559h483" at 6427.76,6252.5 h60
  text "Q" at 68.41,6242.51 h66.67
  text "8" at 603.38,6102.5 h60
  text "28.00mil (0.711mm)" at 1203.22,6102.5 h60
  text "PTH" at 2352.88,6102.5 h60
  text "Round" at 2858.76,6102.5 h60
  text "Top Layer - Bottom Layer" at 3592.56,6102.5 h60
  text "Pad" at 5092.11,6102.5 h60
  text "Rounded" at 5681.96,6102.5 h60
  text "c122h71" at 6427.76,6102.5 h60
  text "K" at 68.41,6092.51 h66.67
  text "8" at 603.38,5952.5 h60
  text "32.00mil (0.813mm)" at 1203.22,5952.5 h60
  text "PTH" at 2352.88,5952.5 h60
  text "Round" at 2858.76,5952.5 h60
  text "Top Layer - Bottom Layer" at 3592.56,5952.5 h60
  text "Pad" at 5092.11,5952.5 h60
  text "(Mixed)" at 5681.96,5952.5 h60
  text "(Mixed)" at 6427.76,5952.5 h60
  text "9" at 603.38,5802.5 h60
  text "40.00mil (1.016mm)" at 1203.22,5802.5 h60
  text "PTH" at 2352.88,5802.5 h60
  text "Round" at 2858.76,5802.5 h60
  text "Top Layer - Bottom Layer" at 3592.56,5802.5 h60
  text "Pad" at 5092.11,5802.5 h60
  text "(Mixed)" at 5681.96,5802.5 h60
  text "(Mixed)" at 6427.76,5802.5 h60
  text "E" at 68.41,5792.51 h66.67
  text "18" at 603.38,5652.5 h60
  text "42.91mil (1.090mm)" at 1203.22,5652.5 h60
  text "PTH" at 2352.88,5652.5 h60
  text "Round" at 2858.76,5652.5 h60
  text "Top Layer - Bottom Layer" at 3592.56,5652.5 h60
  text "Pad" at 5092.11,5652.5 h60
  text "(Mixed)" at 5681.96,5652.5 h60
  text "(Mixed)" at 6427.76,5652.5 h60
  text "18" at 603.38,5502.5 h60
  text "52.00mil (1.321mm)" at 1203.22,5502.5 h60
  text "PTH" at 2352.88,5502.5 h60
  text "Round" at 2858.76,5502.5 h60
  text "Top Layer - Bottom Layer" at 3592.56,5502.5 h60
  text "Pad" at 5092.11,5502.5 h60
  text "Rounded" at 5681.96,5502.5 h60
  text "c190h132" at 6427.76,5502.5 h60
  text "21" at 603.38,5352.5 h60
  text "80.00mil (2.032mm)" at 1203.22,5352.5 h60
  text "PTH" at 2352.88,5352.5 h60
  text "Round" at 2858.76,5352.5 h60
  text "Top Layer - Bottom Layer" at 3592.56,5352.5 h60
  text "Pad" at 5092.11,5352.5 h60
  text "(Mixed)" at 5681.96,5352.5 h60
  text "(Mixed)" at 6427.76,5352.5 h60
  text "I" at 79.52,5342.51 h66.67
  text "149" at 603.38,5202.5 h60
  text "14.00mil (0.356mm)" at 1203.22,5202.5 h60
  text "PTH" at 2352.88,5202.5 h60
  text "Round" at 2858.76,5202.5 h60
  text "Top Layer - Bottom Layer" at 3592.56,5202.5 h60
  text "(Mixed)" at 5092.11,5202.5 h60
  text "Rounded" at 5681.96,5202.5 h60
  text "(Mixed)" at 6427.76,5202.5 h60
  text "243 Total" at 603.38,5052.5 h60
